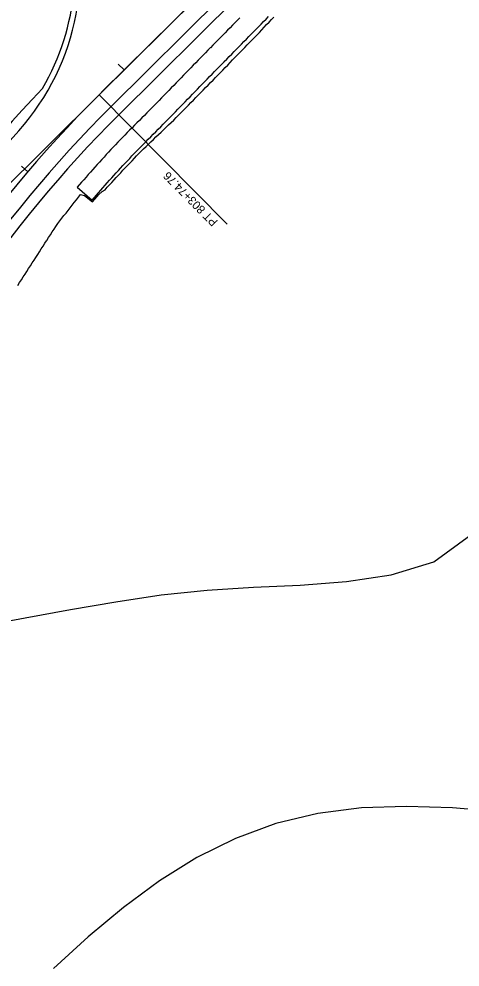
# Model space of a CAD drawing. Extents: x 1237212 to 1293764, y 379349 to 410301.
# Drawn here: x 1283667 to 1283981, y 403888 to 404565 of the extents above; entities that cross this region are included whole.
import ezdxf

# ---------------------------------------------------------------- set-up
doc = ezdxf.new("R2010")
doc.units = 0
for name, color, linetype in [('B-Sub-Pier Cap', 7, 'Continuous'), ('B-Tbl-Title Block', 7, 'Continuous'), ('B-Title Block (No Plot)', 7, 'Continuous'), ('R_Axis_Annotation', 7, 'Continuous'), ('R_Exist Surface', 7, 'Continuous'), ('R_Grid', 7, 'Continuous'), ('R_Grid Annot', 7, 'Continuous'), ('R_Shld', 7, 'Continuous')]:
    doc.layers.add(name, color=color, linetype=linetype)

msp = doc.modelspace()

# ---------------------------------------------------------------- linework, layer by layer
msp.add_lwpolyline([(1283774.89, 404561.11), (1283786.25, 404572.37)])
at = {"layer": 'B-Sub-Pier Cap'}
msp.add_line((1283708.13, 404444.4), (1283718.71, 404435.23), dxfattribs=at)
for points in [[(1283824.22, 404565.41), (1283822.47, 404563.63), (1283820.71, 404561.84), (1283818.95, 404560.06), (1283817.2, 404558.28), (1283815.44, 404556.5), (1283813.69, 404554.71), (1283811.94, 404552.93), (1283810.18, 404551.14), (1283808.43, 404549.36), (1283806.68, 404547.57), (1283804.93, 404545.78), (1283803.18, 404544), (1283803.09, 404543.91), (1283801.43, 404542.21), (1283799.68, 404540.42), (1283797.93, 404538.63), (1283796.18, 404536.84), (1283794.43, 404535.05), (1283792.69, 404533.26), (1283790.94, 404531.47), (1283789.19, 404529.68), (1283787.45, 404527.89), (1283785.7, 404526.09), (1283783.96, 404524.3), (1283782.21, 404522.51), (1283780.47, 404520.71), (1283778.73, 404518.92), (1283776.98, 404517.12), (1283775.24, 404515.33), (1283773.5, 404513.53), (1283771.76, 404511.73), (1283770.02, 404509.94), (1283768.28, 404508.14), (1283766.54, 404506.34), (1283764.83, 404504.57), (1283763.09, 404502.83), (1283761.32, 404501.06), (1283759.56, 404499.29), (1283757.79, 404497.51), (1283756.03, 404495.74), (1283754.26, 404493.97), (1283752.5, 404492.19), (1283750.73, 404490.42), (1283748.97, 404488.65), (1283747.21, 404486.87), (1283745.51, 404485.15), (1283743.82, 404483.43), (1283742.14, 404481.71), (1283740.46, 404479.98), (1283738.79, 404478.25), (1283737.13, 404476.51), (1283735.47, 404474.77), (1283733.81, 404473.02), (1283732.16, 404471.27), (1283730.52, 404469.51), (1283728.88, 404467.75), (1283727.25, 404465.98), (1283725.62, 404464.2), (1283724, 404462.42), (1283722.39, 404460.64), (1283720.78, 404458.85), (1283719.18, 404457.06), (1283717.58, 404455.26), (1283715.99, 404453.45), (1283714.4, 404451.64), (1283712.82, 404449.83), (1283711.24, 404448.01), (1283708.13, 404444.4)], [(1283718.71, 404435.23), (1283721.76, 404438.77), (1283723.31, 404440.56), (1283724.86, 404442.34), (1283726.42, 404444.12), (1283727.98, 404445.89), (1283729.55, 404447.66), (1283731.13, 404449.42), (1283732.71, 404451.18), (1283734.3, 404452.94), (1283735.89, 404454.68), (1283737.49, 404456.43), (1283739.09, 404458.17), (1283740.7, 404459.9), (1283742.32, 404461.63), (1283743.94, 404463.35), (1283745.56, 404465.07), (1283747.19, 404466.78), (1283748.83, 404468.49), (1283750.47, 404470.19), (1283752.12, 404471.89), (1283753.77, 404473.58), (1283755.43, 404475.27), (1283757.1, 404476.96), (1283758.86, 404478.74), (1283760.62, 404480.51), (1283762.39, 404482.28), (1283764.15, 404484.05), (1283765.91, 404485.83), (1283767.68, 404487.6), (1283769.44, 404489.37), (1283771.2, 404491.14), (1283772.97, 404492.91), (1283774.74, 404494.68), (1283776.48, 404496.49), (1283778.22, 404498.29), (1283779.96, 404500.08), (1283781.7, 404501.88), (1283783.44, 404503.67), (1283785.18, 404505.47), (1283786.92, 404507.26), (1283788.66, 404509.06), (1283790.4, 404510.85), (1283792.15, 404512.64), (1283793.89, 404514.44), (1283795.63, 404516.23), (1283797.38, 404518.02), (1283799.12, 404519.81), (1283800.87, 404521.6), (1283802.61, 404523.39), (1283804.36, 404525.18), (1283806.11, 404526.97), (1283807.85, 404528.76), (1283809.6, 404530.54), (1283811.35, 404532.33), (1283813.01, 404534.03), (1283813.1, 404534.12), (1283814.85, 404535.9), (1283816.6, 404537.69), (1283818.35, 404539.47), (1283820.1, 404541.26), (1283821.85, 404543.04), (1283823.6, 404544.82), (1283825.35, 404546.61), (1283827.11, 404548.39), (1283828.86, 404550.17), (1283830.62, 404551.95), (1283832.37, 404553.73), (1283834.13, 404555.51), (1283835.88, 404557.29), (1283837.64, 404559.07), (1283839.4, 404560.85), (1283841.15, 404562.63), (1283842.91, 404564.4), (1283844.68, 404566.19)]]:
    msp.add_lwpolyline(points, dxfattribs=at)
at = {"layer": 'B-Tbl-Title Block'}
msp.add_line((1283732.12, 404501.81), (1283963.1, 404730.79), dxfattribs=at)
for centre, radius, start, end in [((1283535.54, 404600.86), 175, 318.45801, 19.84038), ((1284344.24, 403884.33), 869.47, 134.75, 157.33333), ((1284344.24, 403884.33), 905.47, 138.45801, 157.33333)]:
    msp.add_arc(centre, radius, start, end, dxfattribs=at)
at = {"layer": 'B-Title Block (No Plot)'}
for p, q in [((1283723.67, 404510.34), (1284167.7, 404950.51)), ((1283723.67, 404510.34), (1284167.7, 404950.51)), ((1283725.52, 404512.17), (1284086.2, 404869.72))]:
    msp.add_line(p, q, dxfattribs=at)
msp.add_arc((1284344.24, 403884.33), 881.47, 134.75, 157.33333, dxfattribs=at)
msp.add_arc((1284344.24, 403884.33), 881.47, 134.75, 157.33333, dxfattribs=at)
at = {"layer": 'R_Axis_Annotation'}
for points in [[(1283638.76, 404131.23), (1283670.92, 404137.36), (1283703.24, 404143.19), (1283735.6, 404148.59), (1283768.06, 404153.62), (1283800.82, 404157.07), (1283834.02, 404159.05), (1283867.23, 404160.66), (1283900.19, 404163.19), (1283932.2, 404168.04), (1283962.57, 404177.17), (1283989.1, 404196.54)], [(1284009.33, 403998.89), (1283975.98, 404001.67), (1283943.02, 404002.8), (1283911.02, 404001.73), (1283879.9, 403997.73), (1283849.94, 403990.68), (1283821.07, 403979.97), (1283793.49, 403966.21), (1283766.86, 403949.64), (1283741.03, 403930.57), (1283715.99, 403909.66), (1283691.25, 403887.11)]]:
    msp.add_lwpolyline(points, dxfattribs=at)
at = {"layer": 'R_Exist Surface'}
for points in [[(1283719, 404434.03), (1283720.73, 404436.04), (1283723.58, 404439.35), (1283725.94, 404441.35), (1283727.95, 404442.72), (1283729.56, 404444.44), (1283731.18, 404446.15), (1283732.79, 404447.87), (1283734.36, 404449.63), (1283735.95, 404451.38), (1283737.54, 404453.12), (1283739.14, 404454.85), (1283740.74, 404456.58), (1283742.37, 404458.3), (1283743.99, 404460), (1283745.62, 404461.71), (1283747.25, 404463.42), (1283748.88, 404465.12), (1283750.53, 404466.81), (1283752.2, 404468.48), (1283753.86, 404470.15), (1283755.53, 404471.81), (1283757.21, 404473.47), (1283758.9, 404475.13), (1283760.69, 404476.88), (1283762.49, 404478.62), (1283764.28, 404480.36), (1283766.09, 404482.09), (1283767.91, 404483.8), (1283769.74, 404485.5), (1283771.56, 404487.22), (1283773.37, 404488.95), (1283775.17, 404490.68), (1283776.98, 404492.41), (1283778.74, 404494.18), (1283780.5, 404495.96), (1283782.26, 404497.73), (1283784.02, 404499.51), (1283785.78, 404501.29), (1283787.53, 404503.07), (1283789.27, 404504.86), (1283791.01, 404506.66), (1283792.76, 404508.45), (1283794.5, 404510.25), (1283796.25, 404512.03), (1283798.01, 404513.81), (1283799.78, 404515.58), (1283801.54, 404517.35), (1283803.28, 404519.14), (1283805.03, 404520.93), (1283806.78, 404522.72), (1283808.53, 404524.5), (1283810.28, 404526.29), (1283812.03, 404528.07), (1283813.79, 404529.85), (1283815.53, 404531.64), (1283817.26, 404533.45), (1283818.98, 404535.26), (1283820.71, 404537.07), (1283822.45, 404538.86), (1283824.21, 404540.64), (1283825.97, 404542.42), (1283827.71, 404544.21), (1283829.45, 404546.01), (1283831.18, 404547.81), (1283832.92, 404549.62), (1283834.68, 404551.39), (1283836.45, 404553.15), (1283838.2, 404554.94), (1283839.88, 404556.79), (1283841.56, 404558.65), (1283843.25, 404560.5), (1283845.01, 404562.27), (1283846.79, 404564.03), (1283848.48, 404565.87)], [(1283665.68, 404374.45), (1283666.97, 404376.45), (1283668.26, 404378.45), (1283669.55, 404380.44), (1283670.84, 404382.44), (1283672.13, 404384.44), (1283673.42, 404386.45), (1283674.71, 404388.45), (1283676.01, 404390.45), (1283677.3, 404392.45), (1283678.59, 404394.46), (1283679.89, 404396.46), (1283681.18, 404398.47), (1283682.48, 404400.48), (1283683.78, 404402.48), (1283685.07, 404404.49), (1283686.25, 404406.31), (1283686.37, 404406.5), (1283687.67, 404408.52), (1283688.97, 404410.53), (1283690.27, 404412.54), (1283691.57, 404414.56), (1283692.87, 404416.57), (1283694.22, 404418.55), (1283695.69, 404420.43), (1283697.17, 404422.31), (1283698.64, 404424.19), (1283700.12, 404426.06), (1283701.6, 404427.94), (1283703.07, 404429.82), (1283704.55, 404431.7), (1283706.03, 404433.58), (1283707.5, 404435.46), (1283708.98, 404437.34), (1283710.46, 404439.22), (1283713.26, 404438.63), (1283719, 404434.03)]]:
    msp.add_lwpolyline(points, dxfattribs=at)
at = {"layer": 'R_Grid'}
msp.add_line((1283598.67, 404386.43), (1283723.67, 404510.34), dxfattribs=at)
msp.add_lwpolyline([(1283723.67, 404510.34), (1283815.19, 404418.01)], dxfattribs=at)
msp.add_lwpolyline([(1283723.67, 404510.34), (1283815.19, 404418.01)], dxfattribs=at)
at = {"layer": 'R_Grid Annot'}
for points in [[(1283737.37, 404532.37), (1283741.59, 404528.11)], [(1283737.37, 404532.37), (1283741.59, 404528.11)], [(1283668.3, 404459.4), (1283672.87, 404455.52)], [(1283668.3, 404459.4), (1283672.87, 404455.52)]]:
    msp.add_lwpolyline(points, dxfattribs=at)
at = {"layer": 'R_Shld'}
msp.add_line((1283737.75, 404496.13), (1283826.69, 404584.3), dxfattribs=at)
for centre, radius, start, end in [((1283535.54, 404600.86), 171, 329.85923, 19.84038), ((1284344.24, 403884.33), 913.47, 136.3373, 157.67823), ((1284344.24, 403884.33), 861.47, 134.75, 157.33333)]:
    msp.add_arc(centre, radius, start, end, dxfattribs=at)

# ---------------------------------------------------------------- texts
at = {"layer": 'R_Grid'}
msp.add_text('PT 803+74.76', height=6, rotation=134.75, dxfattribs=at).set_placement((1283808.83, 404420.16))
msp.add_text('PT 803+74.76', height=6, rotation=134.75, dxfattribs=at).set_placement((1283808.83, 404420.16))

doc.saveas('drawing.dxf')
